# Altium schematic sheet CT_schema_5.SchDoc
size 208 x 198 mm
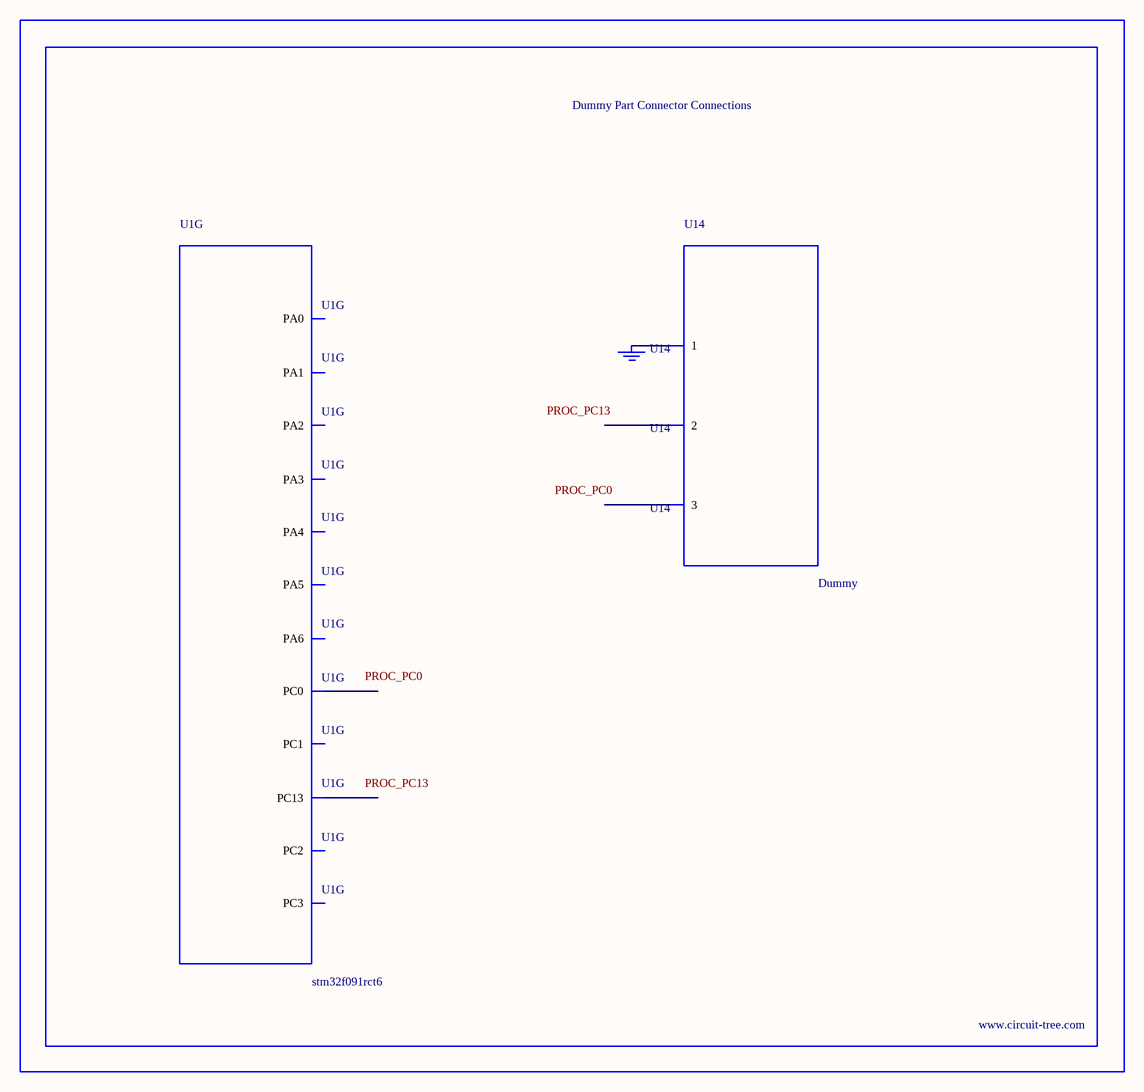
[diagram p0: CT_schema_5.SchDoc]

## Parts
BORDER4  (no value)
GND_INSTANCE_4_0  (no value)
U1  stm32f091rct6  [LQFP64]  (part G of 7)
U14  Dummy  [DUMMY_PACKAGE_129]

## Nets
NetGND_INSTANCE_4_0_0: GND_INSTANCE_4_0.0(GND) U14.1

Not connected (* = marked no-connect by the designer): U1 2(PC13) 8(PC0) 9(PC1) 10(PC2) 11(PC3) 14(PA0) 15(PA1) 16(PA2) 17(PA3) 20(PA4) 21(PA5) 22(PA6); U14 2 3

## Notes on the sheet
- Labels drawn without touching a wire or pin: PROC_PC0, PROC_PC13

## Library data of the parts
BORDER4 = BORDER_PAGE4
GND_INSTANCE_4_0 = GND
